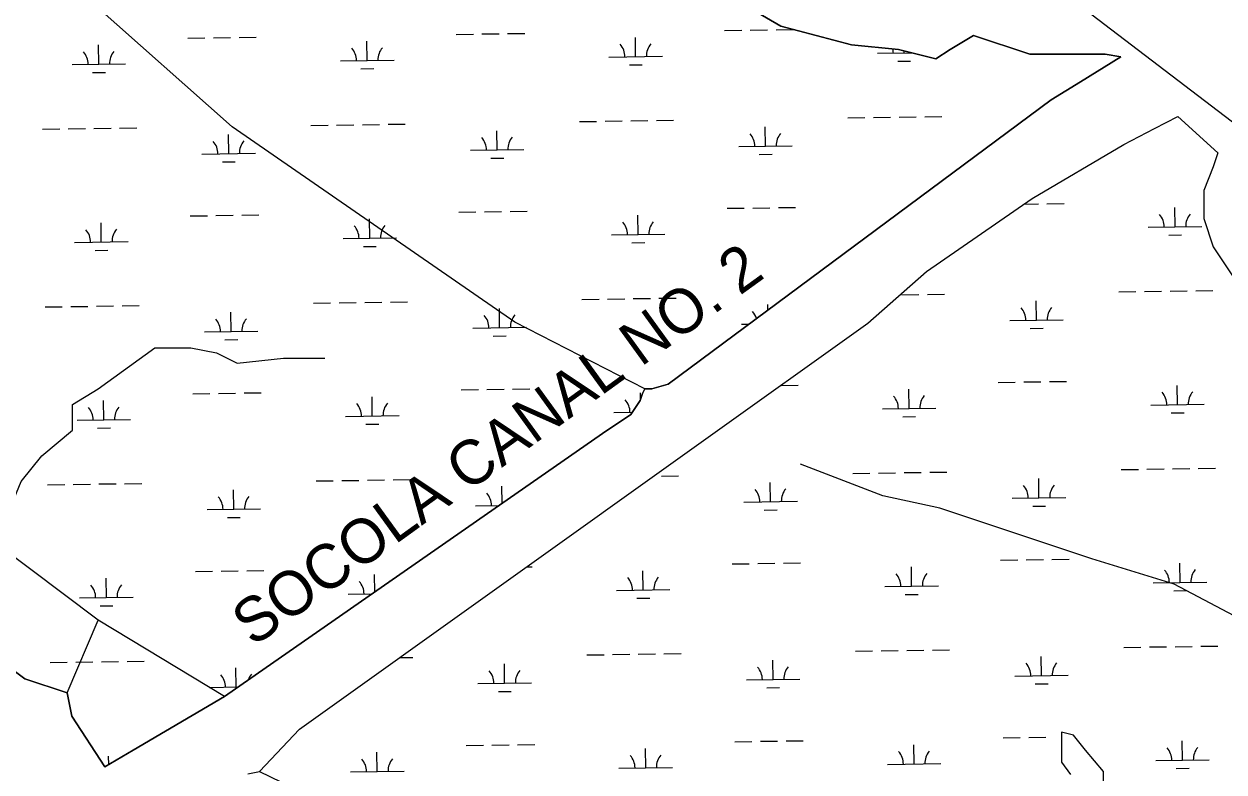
# Model space of a CAD drawing. Extents: x 3775218 to 3813389, y 343470 to 369318.
# Drawn here: x 3781126 to 3783369, y 363812 to 365212 of the extents above; entities that cross this region are included whole.
import ezdxf

# ---------------------------------------------------------------- set-up
doc = ezdxf.new("R2010")
doc.units = 0
for name, color, linetype in [('V-RIVR-IDEN', 7, 'Continuous'), ('V-TOPO-SHOR', 7, 'Continuous'), ('V-UTIL-LINE', 7, 'Continuous'), ('V-WETL-SWMP', 7, 'Continuous')]:
    doc.layers.add(name, color=color, linetype=linetype)

msp = doc.modelspace()

# ---------------------------------------------------------------- linework, layer by layer
at = {"layer": 'V-TOPO-SHOR'}
for p, q in [((3783239.4, 365016.4), (3783283.1, 365039.2)), ((3783283.1, 365039.2), (3783357.7, 364971.1)), ((3783182.1, 364986.5), (3783239.4, 365016.4)), ((3783010.9, 364885.4), (3783182.1, 364986.5)), ((3783357.7, 364971.1), (3783348.9, 364944.7)), ((3783348.9, 364944.7), (3783331.4, 364900.8)), ((3783331.4, 364900.8), (3783331.4, 364848.1)), ((3782813.3, 364749.2), (3783010.9, 364885.4)), ((3783331.4, 364848.1), (3783348.9, 364795.4)), ((3783348.9, 364795.4), (3783401.6, 364716.3)), ((3782703.5, 364652.6), (3782813.3, 364749.2)), ((3782396.2, 364432.9), (3782703.5, 364652.6)), ((3781641.1, 363892.5), (3782396.2, 364432.9)), ((3781500.6, 363954), (3781264.8, 364096.5)), ((3781566.4, 363813.4), (3781641.1, 363892.5)), ((3781544.5, 363809), (3781566.4, 363813.4))]:
    msp.add_line(p, q, dxfattribs=at)
for points in [[(3782286.5, 364529.5), (3782043.8, 364654.3), (3781514.8, 365019.8), (3781255.2, 365250.6), (3781101.3, 365491), (3781005.1, 365712.3), (3780957, 365808.4), (3780889.7, 365895), (3780639.6, 366077.7), (3780399.2, 366241.2), (3780206.8, 366337.4), (3779725.9, 366462.4), (3779398.9, 366549), (3779209.7, 366636.3)], [(3782479.7, 365243.5), (3782541.1, 365208.3), (3782672.8, 365173.2), (3782760.6, 365164.4), (3782830.9, 365146.8), (3782857.2, 365164.4), (3782901.1, 365190.8), (3783006.5, 365155.6), (3783147, 365155.6), (3783176.3, 365150.9)], [(3783176.3, 365150.9), (3783101, 365104.1), (3783046, 365069.9), (3782330.4, 364538.3), (3782299.6, 364529.5), (3782286.5, 364529.5), (3782282.1, 364520.8), (3782277.7, 364507.6), (3782260.1, 364481.2), (3782207.4, 364446.1), (3781500.6, 363954), (3781330, 363853.4), (3781277, 363822.2)], [(3781206.5, 363960.6), (3781264.8, 364096.5), (3781072.4, 364240.8), (3781120.5, 364356.2), (3781159, 364404.3), (3781216.7, 364452.3), (3781216.7, 364500.4), (3781264.8, 364529.3), (3781370.6, 364606.2), (3781437.9, 364606.2), (3781486, 364596.6), (3781524.5, 364577.4), (3781611, 364587), (3781659.1, 364587), (3781688, 364587)], [(3785008.5, 363022.6), (3784908.7, 363146.4), (3784802.2, 363241.1), (3784707.5, 363312.1), (3784636.5, 363371.2), (3784553.7, 363430.4), (3784494.6, 363477.7), (3784435.4, 363513.2), (3784269.8, 363643.3), (3784092.3, 363761.6), (3783997.7, 363820.8), (3783784.7, 363915.4), (3783500.8, 364045.6), (3783276, 364163.9), (3783122.2, 364211.2), (3782980.2, 364258.5), (3782838.2, 364305.9), (3782731.7, 364329.5), (3782577.9, 364388.7)], [(3781277, 363822.2), (3781215.2, 363916.7), (3781206.5, 363960.6), (3781127.4, 363987), (3781092.3, 364013.3), (3781066, 364013.3), (3781013.3, 364004.6), (3780986.9, 364030.9), (3780969.4, 364066.1), (3780925.5, 364101.2), (3780899.1, 364127.6), (3780864, 364145.1), (3780828.9, 364145.1), (3780855.2, 364101.2), (3780872.8, 364039.7), (3780846.4, 364022.1), (3780758.6, 364030.9), (3780714.7, 364057.3), (3780706, 364083.6), (3780670.8, 364118.8), (3780583, 364066.1), (3780547.9, 364057.3), (3780495.2, 364057.3)], [(3783144.3, 363791.1), (3783144.3, 363813.7), (3783110.4, 363853.2), (3783087.9, 363881.4), (3783065.3, 363887), (3783065.3, 363830.6), (3783082.2, 363808.1)], [(3781566.4, 363813.4), (3781686.8, 363754.6), (3781789, 363696.8), (3781860.1, 363621.3), (3781922.3, 363554.7), (3782002.3, 363510.2), (3782113.4, 363439.1), (3782166.7, 363399.1), (3782215.6, 363345.8), (3782260, 363296.9), (3782304.5, 363265.8), (3782353.3, 363234.7), (3782433.3, 363177), (3782553.3, 363119.2)]]:
    msp.add_lwpolyline(points, dxfattribs=at)
at = {"layer": 'V-UTIL-LINE'}
msp.add_lwpolyline([(3780679.3, 367094), (3785426.9, 363471.2), (3792974.2, 356758.7), (3793366, 356995.9), (3793845.8, 357258.7), (3797110.8, 352684.9), (3797510.2, 352064.7), (3798847.9, 350037.3), (3800878.7, 349194.8)], dxfattribs=at)
at = {"layer": 'V-WETL-SWMP'}
for p, q in [((3781432.1, 365185.6), (3781464.1, 365186.1)), ((3781480.1, 365186.3), (3781512.1, 365186.8)), ((3781528.1, 365187), (3781560.1, 365187.4)), ((3781934, 365192.7), (3781966, 365193.2)), ((3781982, 365193.4), (3782014, 365193.8)), ((3782030, 365194.1), (3782062, 365194.5)), ((3782269.4, 365151), (3782268.9, 365187)), ((3782435.8, 365199.8), (3782467.8, 365200.3)), ((3782483.8, 365200.5), (3782515.8, 365200.9)), ((3782531.8, 365201.2), (3782563.8, 365201.6)), ((3781265.7, 365136.9), (3781265.2, 365172.9)), ((3781767.6, 365143.9), (3781767.1, 365179.9)), ((3782771.3, 365158.1), (3782771.2, 365161.7)), ((3781717.6, 365143.2), (3781817.6, 365144.6)), ((3782219.4, 365150.3), (3782319.4, 365151.7)), ((3782721.3, 365157.4), (3782785.1, 365158.3)), ((3782759.5, 365142.5), (3782783.5, 365142.8)), ((3781215.7, 365136.2), (3781315.7, 365137.6)), ((3781253.9, 365121.3), (3781277.9, 365121.6)), ((3781755.8, 365128.3), (3781779.8, 365128.7)), ((3782257.7, 365135.4), (3782281.7, 365135.8)), ((3782164.3, 365029.5), (3782196.3, 365029.9)), ((3782212.3, 365030.1), (3782244.3, 365030.6)), ((3782260.3, 365030.8), (3782292.3, 365031.3)), ((3782308.3, 365031.5), (3782340.3, 365031.9)), ((3782666.2, 365036.5), (3782698.1, 365037)), ((3782714.1, 365037.2), (3782746.1, 365037.7)), ((3782762.1, 365037.9), (3782794.1, 365038.3)), ((3782810.1, 365038.6), (3782842.1, 365039)), ((3783239.4, 365016.4), (3783283.1, 365039.2)), ((3783283.1, 365039.2), (3783357.7, 364971.1)), ((3781160.6, 365015.3), (3781192.6, 365015.7)), ((3781208.6, 365016), (3781240.6, 365016.4)), ((3781256.6, 365016.6), (3781288.6, 365017.1)), ((3781304.6, 365017.3), (3781336.6, 365017.8)), ((3781508.6, 364969.5), (3781508.1, 365005.5)), ((3781662.4, 365022.4), (3781694.4, 365022.8)), ((3781710.4, 365023), (3781742.4, 365023.5)), ((3781758.4, 365023.7), (3781790.4, 365024.2)), ((3781806.4, 365024.4), (3781838.4, 365024.9)), ((3782010.4, 364976.5), (3782009.9, 365012.5)), ((3782512.3, 364983.6), (3782511.8, 365019.6)), ((3783182.1, 364986.5), (3783239.4, 365016.4)), ((3782462.3, 364982.9), (3782562.3, 364984.3)), ((3783010.9, 364885.4), (3783182.1, 364986.5)), ((3781458.6, 364968.7), (3781558.6, 364970.2)), ((3781960.4, 364975.8), (3782060.4, 364977.2)), ((3781998.7, 364960.9), (3782022.7, 364961.3)), ((3782500.5, 364968), (3782524.5, 364968.4)), ((3783357.7, 364971.1), (3783348.9, 364944.7)), ((3781496.8, 364953.9), (3781520.8, 364954.2)), ((3783348.9, 364944.7), (3783331.4, 364900.8)), ((3783331.4, 364900.8), (3783331.4, 364848.1)), ((3782813.3, 364749.2), (3783010.9, 364885.4)), ((3782995.8, 364875), (3783022.4, 364875.4)), ((3783038.4, 364875.6), (3783070.4, 364876)), ((3781436.8, 364853), (3781468.8, 364853.4)), ((3781484.8, 364853.7), (3781516.8, 364854.1)), ((3781532.8, 364854.4), (3781564.8, 364854.8)), ((3781938.7, 364860.1), (3781970.7, 364860.5)), ((3781986.7, 364860.8), (3782018.7, 364861.2)), ((3782034.7, 364861.4), (3782066.6, 364861.9)), ((3782274.1, 364818.4), (3782273.6, 364854.4)), ((3782440.5, 364867.2), (3782472.5, 364867.6)), ((3782488.5, 364867.8), (3782520.5, 364868.3)), ((3782536.5, 364868.5), (3782568.5, 364869)), ((3783277.8, 364832.5), (3783277.3, 364868.5)), ((3783331.4, 364848.1), (3783348.9, 364795.4)), ((3781270.4, 364804.2), (3781269.9, 364840.2)), ((3781772.3, 364811.3), (3781771.8, 364847.3)), ((3783227.8, 364831.8), (3783327.8, 364833.2)), ((3781220.4, 364803.5), (3781320.4, 364804.9)), ((3781722.3, 364810.6), (3781822.3, 364812)), ((3782224.1, 364817.7), (3782324.1, 364819.1)), ((3782262.3, 364802.8), (3782286.3, 364803.1)), ((3783266.1, 364816.9), (3783290.1, 364817.3)), ((3781258.6, 364788.6), (3781282.6, 364789)), ((3781760.5, 364795.7), (3781784.5, 364796)), ((3783348.9, 364795.4), (3783401.6, 364716.3)), ((3782703.5, 364652.6), (3782813.3, 364749.2)), ((3783316.7, 364713), (3783348.7, 364713.5)), ((3781715.1, 364690.4), (3781747.1, 364690.9)), ((3781763.1, 364691.1), (3781795.1, 364691.5)), ((3781811.1, 364691.8), (3781843.1, 364692.2)), ((3782169, 364696.8), (3782201, 364697.3)), ((3782217, 364697.5), (3782249, 364697.9)), ((3782265, 364698.2), (3782297, 364698.6)), ((3782313, 364698.8), (3782345, 364699.3)), ((3782766.8, 364705.2), (3782798.8, 364705.7)), ((3782814.8, 364705.9), (3782846.8, 364706.4)), ((3783018.8, 364658.1), (3783018.3, 364694.1)), ((3783172.7, 364711), (3783204.7, 364711.4)), ((3783220.7, 364711.7), (3783252.7, 364712.1)), ((3783268.7, 364712.3), (3783300.7, 364712.8)), ((3781165.3, 364682.6), (3781197.3, 364683.1)), ((3781213.3, 364683.3), (3781245.3, 364683.8)), ((3781261.3, 364684), (3781293.3, 364684.5)), ((3781309.3, 364684.7), (3781341.3, 364685.1)), ((3781513.3, 364636.8), (3781512.8, 364672.8)), ((3781667.1, 364689.7), (3781699.1, 364690.2)), ((3782015.1, 364643.9), (3782014.6, 364679.9)), ((3782516.6, 364676.7), (3782516.5, 364687)), ((3782396.2, 364432.9), (3782703.5, 364652.6)), ((3782467, 364650.3), (3782481.3, 364650.5)), ((3782968.8, 364657.3), (3783068.8, 364658.8)), ((3781463.3, 364636.1), (3781563.3, 364637.5)), ((3781965.1, 364643.2), (3782065.1, 364644.6)), ((3782003.3, 364628.3), (3782027.3, 364628.6)), ((3783007.1, 364642.5), (3783031.1, 364642.8)), ((3781501.5, 364621.2), (3781525.5, 364621.6)), ((3782541.2, 364535.9), (3782573.2, 364536.3)), ((3782947.1, 364541.6), (3782979.1, 364542.1)), ((3782995.1, 364542.3), (3783027.1, 364542.7)), ((3783043.1, 364543), (3783075.1, 364543.4)), ((3783282.5, 364499.9), (3783282, 364535.9)), ((3781441.5, 364520.4), (3781473.5, 364520.8)), ((3781489.5, 364521), (3781521.5, 364521.5)), ((3781537.5, 364521.7), (3781569.5, 364522.2)), ((3781777, 364478.7), (3781776.5, 364514.7)), ((3781943.4, 364527.4), (3781975.4, 364527.9)), ((3781991.4, 364528.1), (3782023.3, 364528.6)), ((3782039.3, 364528.8), (3782071.3, 364529.2)), ((3782278.5, 364510), (3782278.3, 364521.7)), ((3782780.7, 364492.8), (3782780.2, 364528.8)), ((3781275.1, 364471.6), (3781274.6, 364507.6)), ((3782730.7, 364492.1), (3782830.7, 364493.5)), ((3783232.5, 364499.2), (3783332.5, 364500.6)), ((3781225.1, 364470.9), (3781325.1, 364472.3)), ((3781727, 364477.9), (3781827, 364479.4)), ((3782228.8, 364485), (3782263, 364485.5)), ((3782768.9, 364477.2), (3782792.9, 364477.6)), ((3783270.8, 364484.3), (3783294.8, 364484.6)), ((3781263.3, 364456), (3781287.3, 364456.3)), ((3781765.2, 364463.1), (3781789.2, 364463.4)), ((3781641.1, 363892.5), (3782396.2, 364432.9)), ((3783177.4, 364378.3), (3783209.4, 364378.8)), ((3783225.4, 364379), (3783257.4, 364379.5)), ((3783273.4, 364379.7), (3783305.4, 364380.1)), ((3783321.4, 364380.4), (3783353.4, 364380.8)), ((3781671.8, 364357.1), (3781703.8, 364357.5)), ((3781719.8, 364357.8), (3781751.8, 364358.2)), ((3781767.8, 364358.4), (3781799.8, 364358.9)), ((3781815.8, 364359.1), (3781847.8, 364359.6)), ((3782317.7, 364366.2), (3782349.7, 364366.7)), ((3782521.7, 364318.3), (3782521.2, 364354.3)), ((3782675.5, 364371.3), (3782707.5, 364371.7)), ((3782723.5, 364371.9), (3782755.5, 364372.4)), ((3782771.5, 364372.6), (3782803.5, 364373.1)), ((3782819.5, 364373.3), (3782851.5, 364373.7)), ((3783023.5, 364325.4), (3783023, 364361.4)), ((3781170, 364350), (3781202, 364350.5)), ((3781218, 364350.7), (3781250, 364351.1)), ((3781266, 364351.4), (3781298, 364351.8)), ((3781314, 364352), (3781345.9, 364352.5)), ((3781518, 364304.2), (3781517.5, 364340.2)), ((3782019.8, 364315.4), (3782019.3, 364347.2)), ((3781969.8, 364310.5), (3782013.6, 364311.2)), ((3782471.7, 364317.6), (3782571.7, 364319)), ((3782973.5, 364324.7), (3783073.5, 364326.1)), ((3783011.8, 364309.8), (3783035.8, 364310.2)), ((3781468, 364303.5), (3781568, 364304.9)), ((3781506.2, 364288.6), (3781530.2, 364288.9)), ((3782509.9, 364302.7), (3782533.9, 364303.1)), ((3782449.9, 364201.9), (3782481.9, 364202.3)), ((3782497.9, 364202.6), (3782529.9, 364203)), ((3782545.9, 364203.2), (3782577.9, 364203.7)), ((3782951.8, 364209), (3782983.8, 364209.4)), ((3782999.8, 364209.6), (3783031.8, 364210.1)), ((3783047.8, 364210.3), (3783079.8, 364210.8)), ((3783287.2, 364167.3), (3783286.7, 364203.3)), ((3781279.8, 364138.9), (3781279.3, 364174.9)), ((3781446.2, 364187.7), (3781478.2, 364188.2)), ((3781494.2, 364188.4), (3781526.2, 364188.8)), ((3781542.2, 364189.1), (3781574.2, 364189.5)), ((3781781.6, 364149.6), (3781781.1, 364182)), ((3782065.8, 364196.5), (3782076, 364196.6)), ((3782283.5, 364153.1), (3782283, 364189.1)), ((3782785.4, 364160.2), (3782784.9, 364196.2)), ((3782233.5, 364152.4), (3782333.5, 364153.8)), ((3782735.4, 364159.5), (3782835.4, 364160.9)), ((3783237.2, 364166.6), (3783337.2, 364168)), ((3781229.8, 364138.2), (3781329.8, 364139.6)), ((3781731.7, 364145.3), (3781776.3, 364145.9)), ((3782271.7, 364137.5), (3782295.7, 364137.8)), ((3782773.6, 364144.6), (3782797.6, 364144.9)), ((3783275.4, 364151.7), (3783299.4, 364152)), ((3781268, 364123.3), (3781292, 364123.7)), ((3782776.2, 364040), (3782808.2, 364040.4)), ((3782824.2, 364040.6), (3782856.2, 364041.1)), ((3783182.1, 364045.7), (3783214.1, 364046.1)), ((3783230.1, 364046.4), (3783262.1, 364046.8)), ((3783278.1, 364047), (3783310.1, 364047.5)), ((3783326.1, 364047.7), (3783358.1, 364048.2)), ((3781174.7, 364017.4), (3781206.7, 364017.8)), ((3781222.7, 364018), (3781254.7, 364018.5)), ((3781270.6, 364018.7), (3781302.6, 364019.2)), ((3781318.6, 364019.4), (3781350.6, 364019.8)), ((3781828.5, 364026.6), (3781852.5, 364026.9)), ((3782178.4, 364031.5), (3782210.4, 364032)), ((3782226.4, 364032.2), (3782258.4, 364032.7)), ((3782274.4, 364032.9), (3782306.4, 364033.3)), ((3782322.4, 364033.6), (3782354.4, 364034)), ((3782526.4, 363985.7), (3782525.9, 364021.7)), ((3782680.2, 364038.6), (3782712.2, 364039.1)), ((3782728.2, 364039.3), (3782760.2, 364039.7)), ((3783028.2, 363992.8), (3783027.7, 364028.8)), ((3781522.7, 363971.5), (3781522.1, 364007.5)), ((3782024.5, 363978.6), (3782024, 364014.6)), ((3781974.5, 363977.9), (3782074.5, 363979.3)), ((3782476.4, 363985), (3782576.4, 363986.4)), ((3782978.2, 363992.1), (3783078.2, 363993.5)), ((3783016.4, 363977.2), (3783040.4, 363977.5)), ((3781472.7, 363970.8), (3781525.8, 363971.6)), ((3782012.7, 363963), (3782036.7, 363963.3)), ((3782514.6, 363970.1), (3782538.6, 363970.4)), ((3781566.4, 363813.4), (3781641.1, 363892.5)), ((3781952.7, 363862.2), (3781984.7, 363862.6)), ((3782000.7, 363862.8), (3782032.7, 363863.3)), ((3782048.7, 363863.5), (3782080.7, 363864)), ((3782454.6, 363869.2), (3782486.6, 363869.7)), ((3782502.6, 363869.9), (3782534.6, 363870.4)), ((3782550.6, 363870.6), (3782582.6, 363871)), ((3782790.1, 363827.5), (3782789.6, 363863.5)), ((3782956.5, 363876.3), (3782988.5, 363876.8)), ((3783004.5, 363877), (3783036.4, 363877.4)), ((3783291.9, 363834.6), (3783291.4, 363870.6)), ((3781284.2, 363826.4), (3781284, 363842.3)), ((3781786.3, 363813.4), (3781785.8, 363849.4)), ((3782288.2, 363820.5), (3782287.7, 363856.4)), ((3782238.2, 363819.7), (3782338.2, 363821.2)), ((3782740.1, 363826.8), (3782840.1, 363828.2)), ((3783241.9, 363833.9), (3783341.9, 363835.3)), ((3783280.1, 363819), (3783304.1, 363819.4)), ((3781544.5, 363809), (3781566.4, 363813.4)), ((3781736.4, 363812.7), (3781836.3, 363814.1))]:
    msp.add_line(p, q, dxfattribs=at)
msp.add_lwpolyline([(3781092.3, 364013.3), (3781127.4, 363987), (3781206.5, 363960.6), (3781215.2, 363916.7), (3781277, 363822.2), (3781330, 363853.4), (3781500.6, 363954), (3782207.4, 364446.1), (3782260.1, 364481.2), (3782277.7, 364507.6), (3782282.1, 364520.8), (3782286.5, 364529.5), (3782299.6, 364529.5), (3782330.4, 364538.3), (3783046, 365069.9), (3783101, 365104.1), (3783176.3, 365150.9), (3783147, 365155.6), (3783006.5, 365155.6), (3782901.1, 365190.8), (3782857.2, 365164.4), (3782830.9, 365146.8), (3782760.6, 365164.4), (3782672.8, 365173.2), (3782541.1, 365208.3), (3782479.7, 365243.5)], dxfattribs=at)
for centre, start, end in [((3781712.3, 365143.6), 0.0365, 41.5802), ((3781822.8, 365145.2), 140.0365, 181.5802), ((3782214.2, 365150.7), 0.0365, 41.5802), ((3782324.7, 365152.3), 140.0365, 181.5802), ((3782716, 365157.8), 0.0365, 12.4934), ((3781210.5, 365136.6), 0.0365, 41.5802), ((3781320.9, 365138.1), 140.0365, 181.5802), ((3782457, 364983.3), 0.0365, 41.5802), ((3782567.5, 364984.9), 140.0365, 181.5802), ((3781453.3, 364969.1), 0.0365, 41.5802), ((3781563.8, 364970.7), 140.0365, 181.5802), ((3781955.2, 364976.2), 0.0365, 41.5802), ((3782065.7, 364977.8), 140.0365, 181.5802), ((3782720.7, 364825.2), 40.7356, 41.5802), ((3783222.6, 364832.2), 0.0365, 41.5802), ((3783333.1, 364833.8), 140.0365, 181.5802), ((3781215.2, 364803.9), 0.0365, 41.5802), ((3781325.6, 364805.5), 140.0365, 181.5802), ((3781717, 364811), 0.0365, 41.5802), ((3781827.5, 364812.6), 140.0365, 181.5802), ((3782218.9, 364818.1), 0.0365, 41.5802), ((3782329.4, 364819.6), 140.0365, 181.5802), ((3782461.7, 364650.7), 16.9772, 41.5802), ((3782963.6, 364657.8), 0.0365, 41.5802), ((3783074.1, 364659.3), 140.0365, 181.5802), ((3781458, 364636.5), 0.0365, 41.5802), ((3781568.5, 364638.1), 140.0365, 181.5802), ((3781959.9, 364643.6), 0.0365, 41.5802), ((3782070.4, 364645.1), 140.0365, 181.5802), ((3782725.4, 364492.5), 0.0365, 41.5802), ((3782835.9, 364494.1), 140.0365, 181.5802), ((3783227.3, 364499.6), 0.0365, 41.5802), ((3783337.8, 364501.2), 140.0365, 181.5802), ((3781219.9, 364471.3), 0.0365, 41.5802), ((3781330.3, 364472.8), 140.0365, 181.5802), ((3781721.7, 364478.4), 0.0365, 41.5802), ((3781832.2, 364479.9), 140.0365, 181.5802), ((3782223.6, 364485.4), 0.0365, 41.5802), ((3781964.6, 364310.9), 0.0365, 41.5802), ((3782075.1, 364312.5), 140.0365, 140.2256), ((3782466.4, 364318), 0.0365, 41.5802), ((3782576.9, 364319.6), 140.0365, 181.5802), ((3782968.3, 364325.1), 0.0365, 41.5802), ((3783078.8, 364326.7), 140.0365, 181.5802), ((3781462.7, 364303.9), 0.0365, 41.5802), ((3781573.2, 364305.4), 140.0365, 181.5802), ((3782228.3, 364152.8), 0.0365, 41.5802), ((3782338.7, 364154.3), 140.0365, 181.5802), ((3782730.1, 364159.9), 0.0365, 41.5802), ((3782840.6, 364161.4), 140.0365, 181.5802), ((3783232, 364167), 0.0365, 41.5802), ((3783342.5, 364168.5), 140.0365, 181.5802), ((3781224.6, 364138.6), 0.0365, 41.5802), ((3781335, 364140.2), 140.0365, 181.5802), ((3781726.4, 364145.7), 0.0365, 41.5802), ((3781836.9, 364147.3), 140.0365, 142.806), ((3781577.9, 363972.8), 140.0365, 160.1674), ((3781969.3, 363978.3), 0.0365, 41.5802), ((3782079.7, 363979.9), 140.0365, 181.5802), ((3782471.1, 363985.4), 0.0365, 41.5802), ((3782581.6, 363986.9), 140.0365, 181.5802), ((3782973, 363992.5), 0.0365, 41.5802), ((3783083.5, 363994), 140.0365, 181.5802), ((3781467.4, 363971.2), 0.0365, 41.5802), ((3782233, 363820.1), 0.0365, 41.5802), ((3782343.4, 363821.7), 140.0365, 181.5802), ((3782734.8, 363827.2), 0.0365, 41.5802), ((3782845.3, 363828.8), 140.0365, 181.5802), ((3783236.7, 363834.3), 0.0365, 41.5802), ((3783347.2, 363835.9), 140.0365, 181.5802), ((3781731.1, 363813.1), 0.0365, 41.5802), ((3781841.6, 363814.6), 140.0365, 181.5802)]:
    msp.add_arc(centre, 35.2, start, end, dxfattribs=at)

# ---------------------------------------------------------------- texts
at = {"layer": 'V-RIVR-IDEN'}
msp.add_text('SOCOLA CANAL NO. 2', height=83, rotation=35.875, dxfattribs=at).set_placement((3781554.2, 364045.3))

doc.saveas('drawing.dxf')
